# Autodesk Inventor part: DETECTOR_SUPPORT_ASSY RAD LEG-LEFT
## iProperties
Shininess: 64.0
Length Units: 11272
Angle Units: 11279
Time Units: 11290
Mass Units: 11286
Length Display Precision: 3
Angle Display Precision: 2
Compacted: True
Part Number: DETECTOR_SUPPORT_ASSY RAD LEG-LEFT
Document SubType Name: Modeling
Created: 2004-08
Designer: John Blackburn
Material: ALUMINUM
Manufacturer: Standard
Standards Organization: Custom
Density: 0.0
Volumn: 0.0
Area: 0.0
PropertySet Name: Model Information
Control State: 0
Master: False
Checked Out: False
Author: John Blackburn
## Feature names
1. ExtrusionBlind1
2. SurfCut1_2
3. AM_HOLE_SI0029_1 [Hole]
4. Hole1
5. Hole2
6. AM_HOLE_SI0029_2 [Hole]
7. Hole3
8. Hole4
